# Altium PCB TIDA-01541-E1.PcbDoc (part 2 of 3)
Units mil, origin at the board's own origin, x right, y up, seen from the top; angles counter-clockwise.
Board outline 6299.21 x 6141.73 mil, 4 copper layers (Top Layer, GND, PWR, Bottom Layer), stack 79.834 mil thick; 369 components, 173 nets, 884 pads, 265 vias.
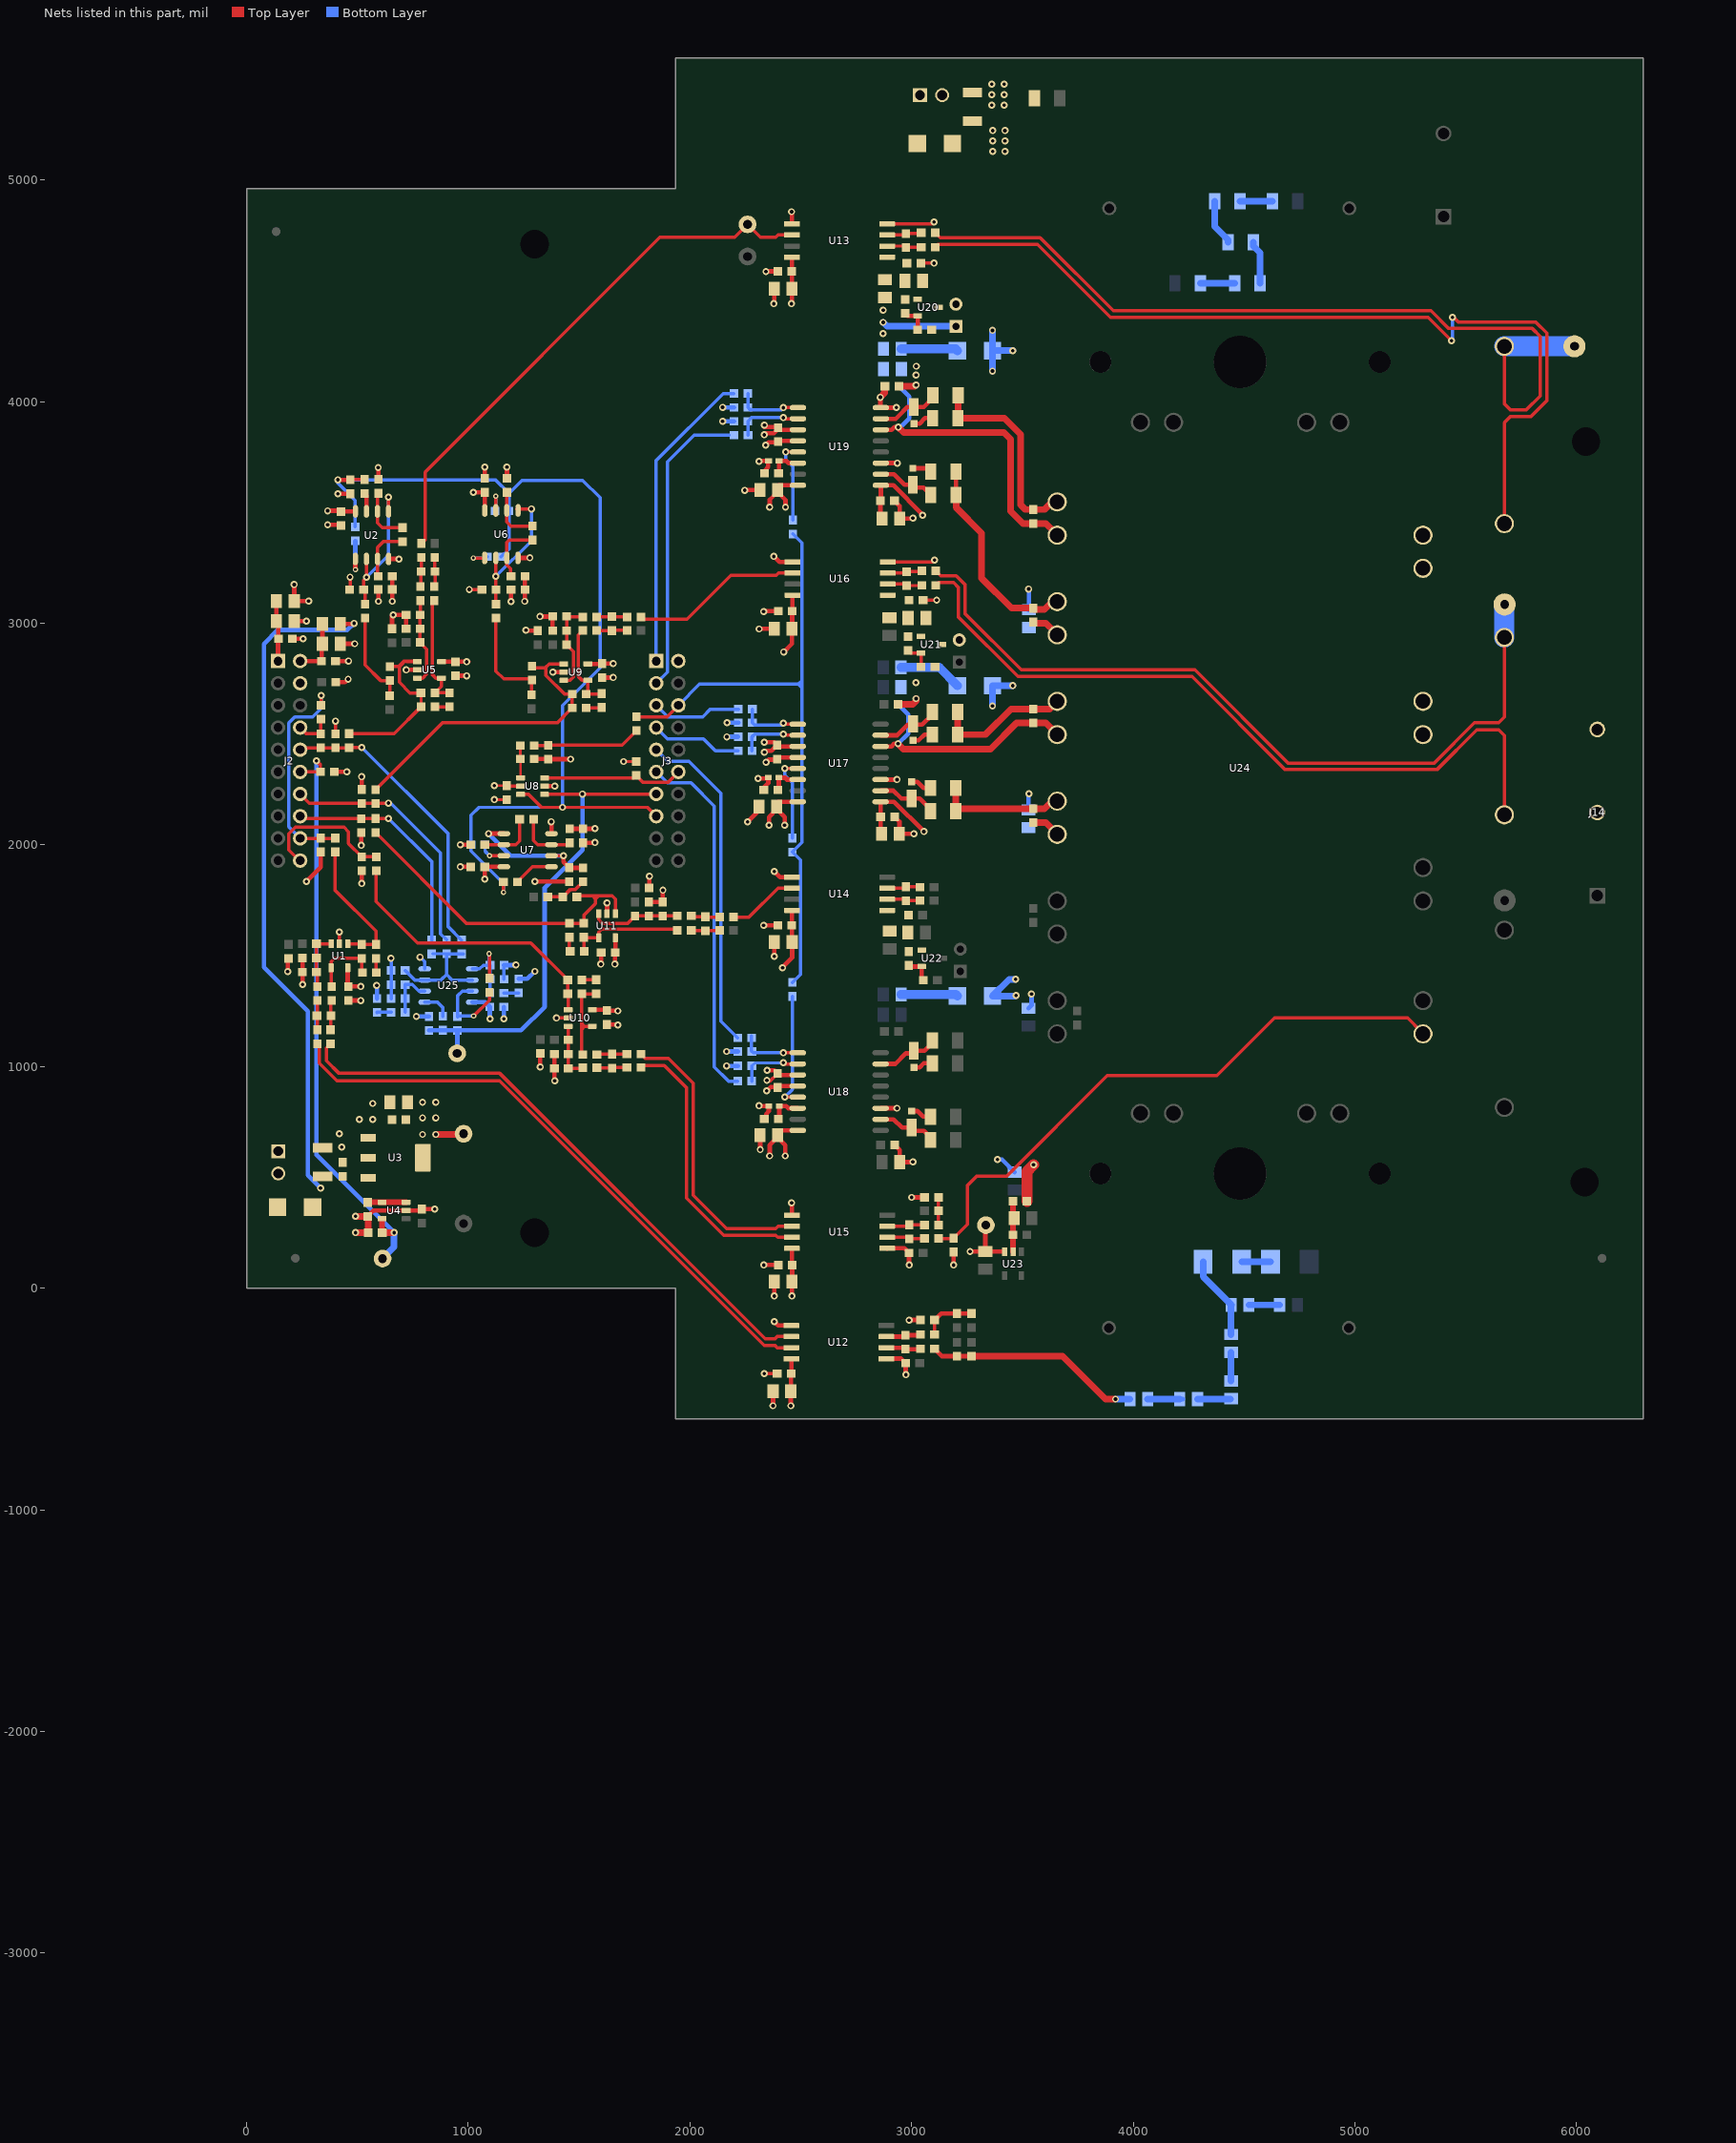
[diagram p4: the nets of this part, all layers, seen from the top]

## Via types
v1: diameter 32, hole 16, Top Layer to Bottom Layer, 258 vias
v2: diameter 24, hole 12, Top Layer to Bottom Layer, 7 vias

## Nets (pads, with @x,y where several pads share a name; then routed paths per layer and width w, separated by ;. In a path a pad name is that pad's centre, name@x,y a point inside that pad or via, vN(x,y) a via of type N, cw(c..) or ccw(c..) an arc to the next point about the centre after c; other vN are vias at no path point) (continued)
3V3: C13.1 C15.1 C23.1 C24.1 C25.1 C31.1 C32.1 C34.1 C35.1 C36.1 C44.1 C47.1 C48.1 C49.1 C55.1 C56.1 C57.1 C58.2 C59.2 C60.2 C61.2 C62.2 C63.2 C64.1 C65.2 C66.2 C67.1 C68.1 C69.2 C70.2 C108.2 R1.1 R11.2 R20.2 R35.2 R48.2 R145.1 R154.2 R157.1 TP4.1 U1.5 U2.8 U3.2 U3.4 U5.5 U6.8 U7.8 U8.5 U9.5 U10.5 U11.5 U12.8 U13.8 U14.8 U15.8 U16.8 U17.3 U17.8 U18.3 U18.8 U19.3 U19.8 U25.8 | length 4833.2
  Top Layer w12: v1(1117.08,2267.23) C36.1@1173.57,2267.23
  Top Layer w15: C36.1@1173.57,2267.23 1175.8,2265 U8.5@1235.87,2265 ; v1(2347,938) 2354.96,938 2359.86,933.1 C67.1@2395.12,968.36
  Top Layer w20: v1(214.73,3174.45) R1.1@214.73,3099.45 v1(279.73,3099.45) ; v1(365.51,3507.34) C13.1@422.01,3507.34 ; v1(411.76,3584.05) R11.2@468.27,3584.05 ; C13.1@425.51,3503.84 426.3,3504.62 U2.8@490.51,3504.62 ; U1.5@456.13,1445.27 456.13,1363.5 C15.1@458.73,1360.9 v1(515.23,1360.9) ; R20.2@657.01,3212.34 657.01,3099.34 v1(657.43,3098.91) ; U5.5@878.87,2826.85 C31.1@940.83,2826.85 ; C31.1@941.73,2825.95 v1(992.24,2825.95) ; v1@1000.83,2826.85 v1@1001.73,2825.95 ; v1@1020.79,3589.84 1021.21,3590.26 C34.1@1074.21,3590.26 U6.8@1074.21,3509.04 ; v1(1074.38,1845.91) C32.1@1074.38,1901.41 ; C32.1@1074.38,1900.91 U7.8@1160.6,1900.91 ; v1(1254.21,3098.77) 1255.71,3100.26 C35.1@1255.71,3151.76 R35.2@1255.71,3211.76 ; R48.2@1457.88,2072.4 C44.1@1517.88,2072.4 1570.41,2072.4 v1(1571.44,2073.43) ; U9.5@1539.2,2816.52 1601.97,2816.52 C48.1@1603.26,2817.81 ; U10.5@1558.87,1256.31 1620.83,1256.31 C49.1@1624.73,1252.4 1673.24,1252.4 v1(1674.73,1250.91) ; C48.1@1602.36,2818.72 C48.1@1603.26,2817.81 ; v1(1653.76,2817.81) C48.1@1603.26,2817.81 ; v1(1660.96,1461.91) 1662.45,1463.41 C47.1@1662.45,1514.91 1663.36,1515.81 U11.5@1663.36,1580.77 ; v1(2335,2463) 2379.68,2463 C64.1@2392.73,2449.95 ; v1(2335,3850) 2342.19,3857.19 2379,3857.19 2395.99,3874.18 2395.99,3878.95 2402.49,3872.45 U19.3@2486.98,3872.45 ; v1@2335,3885 C68.1@2389.94,3885 ; v1(2336,2418) 2342.64,2424.64 2368,2424.64 2392.73,2449.37 C64.1@2392.73,2449.95 ; v1(2348,983) 2380.48,983 C67.1@2395.12,968.36 ; v1(2356.48,2088.46) 2356.48,2125.48 2391.73,2160.73 C56.1@2391.73,2172.45 2391.73,2160.72 2426.99,2125.46 v1(2426.99,2088.46) ; v1(2359.61,596.86) 2359.61,645.6 C55.1@2394.86,680.85 ; v1(2359.73,3524) 2359.73,3557.18 C57.1@2394.99,3592.44 ; C55.1@2394.86,688.86 C55.1@2394.86,680.85 ; C57.1@2394.99,3600.45 C57.1@2394.99,3592.44 ; C56.1@2395.73,2194.45 U17.8@2485.98,2194.45 ; C55.1@2395.86,711.86 U18.8@2486.11,711.86 ; C67.1@2398.36,961.86 U18.3@2486.11,961.86 ; C64.1@2399.23,2443.45 C64.1@2398.23,2444.45 ; C57.1@2399.99,3622.45 U19.8@2486.98,3622.45 ; v1(2417.73,1445.45) 2417.73,1448.45 2460.73,1491.45 C62.2@2460.73,1561.45 2459.23,1562.95 C66.2@2459.23,1637.45 2460.17,1638.39 U14.8@2460.17,1704.45 ; v1(2422.73,2870.45) 2459.73,2907.45 C60.2@2459.73,2974.45 2461.23,2975.95 C69.2@2461.23,3054.45 2462.51,3055.73 U16.8@2462.51,3126.32 ; v1(2430.12,596.86) 2430.12,645.6 C55.1@2394.86,680.85 ; v1(2431,3524) 2431,3556.43 C57.1@2394.99,3592.44 ; v1(2454.73,-530.55) C58.2@2454.73,-465.55 2456.23,-464.05 C63.2@2456.23,-385.55 ; C63.2@2457.17,-385.55 U12.8@2457.17,-318.55 ; v1(2457.73,4441.45) 2459.73,4443.45 C59.2@2459.73,4509.45 2459.73,4586.95 C65.2@2459.23,4587.45 2460.17,4588.39 U13.8@2460.17,4651.58 ; v1(2459.73,-35.55) C61.2@2459.73,29.45 2461.23,30.95 C70.2@2461.23,104.45 2460.17,105.51 U15.8@2460.17,179.45 ; U17.3@2485.98,2444.45 C64.1@2398.23,2444.45 ; C64.1@2392.73,2449.95 C64.1@2398.23,2444.45
  Top Layer w30: v1(853.73,693.45) 975.73,693.45 TP4.1@978.73,696.45
  Bottom Layer w20: v1(586.76,1366.45) 587.76,1365.45 R157.1@587.76,1306.95 ; v1(765.76,1226.45) 765.25,1225.95 R154.2@822.76,1225.95 ; U25.8@1018.04,1290.45 1075.78,1290.45 C108.2@1097.24,1268.99 1097.24,1215.97 v1(1097.76,1215.45) ; R145.1@1227.73,1395.49 1265.77,1395.49 v1(1299.73,1429.45)
  other v1: 793.73,693.45 793.73,768.45 853.73,768.45 793.73,838.45 853.73,838.45 1022.79,3589.84 2336,3894
3V3_REF: C7.1 C22.1 J2.12 TP1.1 U4.5 | length 2679.6
  Top Layer w15: J2.12@241.73,2329.45 C7.1@333.24,2329.45 333.24,2360.95 v1(314.73,2379.45)
  Top Layer w20: C22.1@611.24,251.24 C22.1@611.87,250.61
  Top Layer w25: C22.1@611.24,251.24 U4.5@611.24,313.21
  Top Layer w30: C22.1@611.87,250.61 v1(665.38,250.61)
  Bottom Layer w20: v1@315.73,2378.45 v1(314.73,2379.45) 314.73,601.25 v1(665.38,250.61)
  Bottom Layer w30: TP1.1@613.38,133.61 665.38,185.61 v1(665.38,250.61)
3V3_VDC: C82.2 C91.2 C95.1 R81.1 R90.1 R106.1 TP7.1 U12.1 U15.1 U23.3 | length 757.9
  Top Layer w20: U12.1@2886.3,-318.55 2887.12,-317.73 2952.42,-317.73 C82.2@2973.24,-338.55 2973.24,-390.05 v1(2973.73,-390.55) ; U15.1@2889.3,179.45 2890.12,180.27 2967.42,180.27 C91.2@2988.24,159.45 2988.24,105.95 v1(2989.73,104.45) ; v1(2988.24,-144.05) 2988.73,-143.55 R81.1@3040.24,-143.55 ; v1(2999.73,409.45) R90.1@3058.24,409.45 ; v1(3189.73,104.45) R106.1@3189.73,162.95 ; v1(3263.33,165.32) C95.1@3332.33,165.32 ; TP7.1@3334.73,284.45 3332.33,282.05 C95.1@3332.33,165.32 ; U23.3@3419.93,164.45 3419.06,165.32 C95.1@3332.33,165.32
5V0: C5.1 C14.1 C21.1 D1.1 R7.2 U3.3 U4.3 U4.4 | length 3244.3
  Top Layer w20: R7.2@421.73,2996.45 481.73,2996.45 v1(484.73,2999.45) ; C21.1@546.38,387.1 C21.1@547.28,388.01
  Top Layer w25: C21.1@547.28,388.01 U4.4@611.24,388.01 U4.3@719.51,388.01
  Bottom Layer w20: v1(333.73,451.45) 276,509.18 276,1249 78,1447 78,2907 141,2970 455.28,2970 v1(484.73,2999.45)
+16V_GPS: C71.2 C72.2 C73.2 C74.2 C75.2 C76.2 C93.1 D8.1 D12.2 D13.2 D14.2 R110.1 U17.11 U18.11 U19.11 | length 1549
  Top Layer w20: U17.11@2860,2294.45 v1(2934,2294.45) ; U18.11@2860.12,811.86 v1(2934.13,811.86) ; U19.11@2861,3722.45 v1(2935,3722.45) ; C72.2@2922.23,3552.45 2945.73,3528.95 C73.2@2945.73,3472.45 3003.73,3472.45 v1(3005.73,3474.45) ; C74.2@2923.23,2126.45 2944.73,2104.95 C71.2@2944.73,2049.45 v1(3009.73,2049.45) ; C76.2@2923.36,645.86 2945.86,623.36 C75.2@2945.86,568.86 3004.15,568.86 v1(3005.73,570.45)
  Top Layer w50: R110.1@3519.83,392.32 3519.83,527.54 v1(3549.73,557.45)
  Bottom Layer w30: v1(3364.47,2626.71) D13.2@3364.47,2718.45 v1(3456.21,2718.45) ; v1(3364.47,4137.71) D12.2@3364.47,4229.45 ; v1(3364.47,4321.19) D12.2@3364.47,4229.45 ; v1(3456.21,4229.45) D12.2@3364.47,4229.45 ; v1(3468.73,1393.45) 3439.47,1393.45 D14.2@3364.47,1318.45 3468.73,1318.45 v1(3470.73,1320.45)
  other v1: 3365.73,5128.45 3420.73,5128.45 3365.73,5175.45 3420.73,5175.45 3365.73,5222.45 3420.73,5222.45
DISABLE: J3.6 R164.1 R165.1 R166.1 R167.2 | length 2948.1
  Top Layer w15: R167.2@1759,2578.5 1760.05,2577.45 1895.73,2577.45 J3.6@1947.73,2629.45 J3.6@1947.73,2621.45
  Bottom Layer w15: J3.6@1947.73,2629.45 2043.28,2725 2505,2725 ; R165.1@2462,1379.5 2498,1415.5 2498,1931.5 R166.1@2462,1967.5 2505,2010.5 2505,2725 ; R164.1@2464.73,3402.5 2505,3362.24 2505,2725 ; 2505,2709 2489,2725 2505,2741
DISABLE1: C46.1 R43.2 R167.1 | length 489.6
  Top Layer w15: R43.2@1297.23,2448.23 1359.24,2448.23 C46.1@1360.73,2449.72 1693.22,2449.72 R167.1@1759,2515.5
GND: C1.1 C2.1 C3.1 C4.2 C5.2 C7.2 C8.2 C9.2 C10.2 C11.2 C12.2 C13.2 C14.2 C15.2 C16.2 C17.2 C19.2 C20.2 C21.2 C22.2 C23.2 C24.2 C25.2 C26.1 C27.2 C30.2 C31.2 C32.2 C33.2 C34.2 C35.2 C36.2 C37.1 C38.1 C39.2 C40.2 C42.2 C44.2 C46.2 C47.2 C48.2 C49.2 C52.1 C53.2 C55.2 C56.2 C57.2 C58.1 C59.1 C60.1 C61.1 C62.1 C63.1 C64.2 C65.1 C66.1 C67.2 C68.2 C69.1 C70.1 C101.2 C102.2 C103.2 C104.2 C105.2 C106.2 C107.1 C108.1 C109.1 C110.1 C113.2 C114.2 C115.2 J1.1 J2.4 J3.2 R3.1 R21.1 R24.1 R32.1 R34.1 R39.1 R42.1 R44.1 R63.1 R64.1 R69.1 R70.1 R71.1 R146.2 R155.2 U1.2 U2.4 U3.1 U4.2 U5.2 U6.4 U7.4 U8.2 U9.2 U10.2 U11.2 U12.5 U13.5 U14.5 U15.5 U16.5 U17.4 U18.4 U19.4 U25.4 | length 6638.2
  Top Layer w12: v1(1117.08,2204.24) C36.2@1173.57,2204.24 C36.2@1174.33,2203.48
  Top Layer w15: C12.2@400.73,2500.95 v1(400.73,2558.45) ; U1.2@418.73,1553.54 v1(418.73,1606.4) ; C16.2@465.25,3150.95 466.76,3152.46 v1(466.76,3208.21) ; v1(1004.5,3152.19) C33.2@1061.32,3152.19 ; v1(1397.73,1218.91) U10.2@1450.6,1218.91 ; v1(1700.23,2375.95) R63.1@1757.73,2375.95 ; v1(2334.73,-385.55) C63.1@2393.24,-385.55
  Top Layer w20: C3.1@181.72,1487.91 185.23,1484.4 v1(185.23,1427.91) ; C2.1@206.23,2929.45 v1(254.73,2929.45) ; C1.1@214.73,3009.45 v1(269.73,3009.45) ; v1(252.23,1369.91) C4.2@252.23,1426.4 R3.1@252.23,1489.4 ; v1(269.73,1834.45) 334.73,1899.45 C9.2@334.73,1967.95 ; v1(365.51,3444.35) C13.2@422.01,3444.35 ; C7.2@396.23,2329.45 v1(451.73,2329.45) ; C11.2@401.23,2829.45 v1(459.73,2829.45) ; C8.2@401.5,2734 444,2734 v1(458,2748) ; C10.2@421.73,2907.45 v1(487.73,2907.45) ; C15.2@456.13,1300.5 C15.2@458.73,1297.91 v1(515.23,1297.91) ; v1(517.73,1997.45) C17.2@517.73,2054.95 ; C19.2@518.73,2249.95 v1(518.73,2307.45) ; v1(519.73,1825.45) C20.2@519.73,1882.95 ; C21.2@548.88,321.61 C21.2@546.38,324.11 571.69,349.42 572.54,349.42 573.72,350.61 U4.2@719.51,350.61 783.88,350.61 C30.2@790.38,357.1 v1(848.87,357.1) ; v1(593.66,3702.34) 594.09,3701.91 R21.1@594.09,3648.91 ; C23.2@594.02,3152.34 594.02,3099.34 v1(594.44,3098.91) ; U2.4@640.51,3290.06 687.13,3290.06 v1(687.73,3289.45) ; C26.1@655.73,2974.95 655.73,3031.45 v1(661.73,3037.45) C27.2@719.24,3037.45 R24.1@719.24,2975.45 ; v1(720.1,2789.45) U5.2@770.6,2789.45 ; C31.2@941.73,2762.95 v1(992.24,2762.95) ; v1(963.92,1900.91) C32.2@1011.39,1900.91 ; v1(963.92,2000.91) R32.1@1011.39,2000.91 ; v1@1073.79,3706.68 1074.21,3706.25 C34.2@1074.21,3653.25 ; v1@1173.79,3706.68 1174.21,3706.25 R34.1@1174.21,3653.25 ; C35.2@1192.72,3151.76 1192.72,3098.76 v1(1193.14,3098.33) ; U6.4@1224.21,3294.47 1277.21,3294.47 v1(1277.64,3294.9) ; v1(1260.07,2968.11) 1261.57,2966.62 C37.1@1313.06,2966.62 C37.1@1313.57,2966.11 ; R44.1@1297.23,2388.23 1359.24,2388.23 C46.2@1360.73,2386.73 v1(1461.73,2386.73) ; v1(1299.73,1834.45) v1(1299.73,1834.45) C42.2@1454.96,1834.41 ; v1(1323.06,3030.12) C39.2@1380.54,3030.12 ; v1(1324.73,997.91) 1323.24,999.41 1323.24,1057.91 C38.1@1324.73,1059.41 ; U8.2@1344.13,2265 v1(1390,2265) ; v1(1374.14,2104.46) 1375.17,2103.44 U7.4@1375.17,2050.91 ; R39.1@1380.57,2966.12 1380.57,3030.14 C39.2@1381.04,3030.62 ; v1(1381.43,2779.12) U9.2@1431.93,2779.12 ; R42.1@1388.24,1055.91 C40.2@1388.24,990.91 1388.24,937.4 v1(1389.73,935.91) ; C44.2@1517.88,2009.41 1570.41,2009.41 v1(1571.44,2010.43) ; v1(1597.96,1461.91) 1599.46,1463.41 C47.2@1599.46,1514.91 ; C48.2@1603.26,2754.82 v1(1653.76,2754.82) ; C49.2@1624.73,1189.41 1673.24,1189.41 v1(1674.73,1187.91) ; U11.2@1625.96,1688.04 v1(1625.96,1738.54) ; R64.1@1814.41,1742.4 C53.2@1876.41,1742.4 1876.41,1793.9 v1(1877.91,1795.39) ; C52.1@1815.4,1805.4 C52.1@1815.91,1805.91 1815.91,1857.4 v1(1817.4,1858.9) ; v1(2247.49,3599.95) 2247.99,3600.45 C57.2@2314.99,3600.45 C57.2@2317.99,3597.45 ; v1(2260,2104) 2311.73,2155.73 C56.2@2311.73,2172.45 ; v1(2307,2300) 2350.38,2300 C115.2@2353.38,2303 2353.38,2279.38 2333.24,2259.24 R70.1@2333.24,2247.45 ; v1(2311,823) 2313,821 C114.2@2355.38,821 2355.38,797.38 2343,785 ; v1(2311,3730) 2314,3733 C113.2@2354.38,3733 2353,3731.62 2353,3704 2336.5,3687.5 R71.1@2336.5,3677 ; v1(2312.23,2973.95) 2312.73,2974.45 C60.1@2379.73,2974.45 C60.1@2382.73,2971.45 ; v1(2316.86,624.86) C55.2@2316.86,688.86 ; v1(2332.24,1637.45) C66.1@2396.24,1637.45 ; v1(2332.24,3052.71) 2333.98,3054.45 C69.1@2398.24,3054.45 C69.1@2395.24,3051.45 ; v1(2333.24,104.45) C70.1@2398.24,104.45 C70.1@2399.73,102.95 ; R69.1@2335.37,763.86 2343,771.5 2343,785 ; v1(2341,3803) 2354,3816 2395.94,3816 2395.99,3815.95 2402.49,3822.45 U19.4@2486.98,3822.45 ; v1(2342.73,4586.45) 2343.73,4587.45 C65.1@2396.24,4587.45 ; 2343,785.56 2343,785 ; v1(2343,2373) 2354.45,2384.45 2390.23,2384.45 C64.2@2392.73,2386.95 ; v1@2346,892 v1(2346,891) 2348.08,891 2364.08,907 2393.48,907 C67.2@2395.12,905.37 2401.61,911.86 U18.4@2486.11,911.86 ; v1(2374.73,-530.55) C58.1@2374.73,-465.55 ; v1(2377.73,4441.45) 2379.73,4443.45 C59.1@2379.73,4509.45 ; v1(2378.73,3301.45) 2403.86,3276.32 U16.5@2462.51,3276.32 ; v1(2379.73,-150.55) 2397.73,-168.55 U12.5@2457.17,-168.55 ; v1(2379.73,-35.55) C61.1@2379.73,29.45 C61.1@2381.23,30.95 ; v1(2380.73,1497.45) C62.1@2380.73,1561.45 ; v1(2380.73,1880.45) 2406.73,1854.45 U14.5@2460.17,1854.45 ; C64.2@2400.23,2394.45 U17.4@2485.98,2394.45 ; v1(2458.67,384.45) 2460.17,382.95 U15.5@2460.17,329.45 ; v1(2458.67,4856.58) 2460.17,4855.08 U13.5@2460.17,4801.58
  Top Layer w30: v1(490.87,324.11) C21.2@546.38,324.11 ; v1(491.38,250.61) C22.2@548.88,250.61 C21.2@548.88,321.61
  Bottom Layer w15: v1(651.26,1487.95) 652.26,1486.95 C109.1@652.26,1433.45 C110.1@652.26,1369.45 R155.2@652.26,1306.45 ; v1(782.76,1493.45) 803.47,1472.73 U25.4@803.47,1440.45 ; R146.2@1161.23,1393.99 C107.1@1161.23,1456.99
  Bottom Layer w20: C108.1@1160.23,1268.99 1160.23,1215.97 v1(1160.75,1215.45) ; C107.1@1161.23,1456.99 1214.21,1456.99 v1(1215.19,1457.97) ; v1(2147.19,3910.99) C106.2@2198.24,3910.99 ; v1(2147.19,3973.99) C105.2@2198.24,3973.99 ; v1(2165.19,1002.99) C104.2@2216.24,1002.99 ; v1(2165.19,1067.99) C103.2@2216.24,1067.99 ; v1(2166.19,2487.65) C102.2@2217.24,2487.65 ; v1(2167.19,2550.99) C101.2@2218.24,2550.99
  other v1: 428.73,636.45 418.73,696.45 508.73,761.45 568.73,761.45 568.73,833.45 1074.15,3704.65 1174.15,3704.65
GND1: C93.2 J4.2 R111.1 R132.2 R133.2 R134.2 R135.2 | length 345.9
  Bottom Layer w20: v1@3383.73,576.45 v1(3387.73,580.45) 3407.73,580.45 R135.2@3464.73,523.45 ; R134.2@3527.73,1262.45 3540.73,1275.45 v1(3540.73,1327.45) ; R133.2@3527.73,2157.45 3527.73,2229.45 v1(3528.73,2230.45) ; R132.2@3527.73,3059.45 R132.2@3528.73,3060.45 3528.73,3153.45 v1(3527.73,3154.45)
  other v1: 3361.73,5337.45 3416.73,5337.45 3361.73,5384.45 3416.73,5384.45 3361.73,5431.45 3416.73,5431.45
GND_FAULT: J3.13 R149.2 R152.2 R154.1 TP2.1 U8.1 | length 2197.2
  Top Layer w15: U8.1@1344.13,2227.6 1512.88,2227.6 v1(1514.73,2229.45) J3.13@1847.73,2229.45
  Bottom Layer w20: R154.1@822.76,1162.95 823.31,1163.5 R152.2@885,1163.5 ; R152.2@885,1163.45 942.26,1163.45 R149.2@942.76,1162.95 ; TP2.1@949.73,1059.45 950.73,1060.45 R149.2@950.73,1162.95 1238.24,1162.95 1344.73,1269.45 1344.73,1806.4 1514.73,1976.4 v1(1514.73,2229.45)
I_U: C12.1 J2.10 R6.2 R13.2 R148.1 | length 1337
  Top Layer w15: J2.10@241.73,2429.45 250.24,2437.95 R6.2@334.73,2437.95 C12.1@400.73,2437.95 461.73,2437.95 R13.2@462.73,2438.95 463.23,2439.45 v1(519.73,2439.45)
  Bottom Layer w15: v1(519.73,2439.45) 909.73,2049.45 909.73,1630.95 R148.1@969.73,1570.95
I_V: C19.1 J2.14 R17.2 R150.1 | length 1153.3
  Top Layer w15: J2.14@241.73,2229.45 283.23,2187.95 507.74,2187.95 C19.1@518.73,2176.95 ; C19.1@518.73,2186.95 R17.2@580.73,2186.95 ; R17.2@581.73,2185.95 R17.2@580.73,2186.95 ; v1(639.73,2188.46) 582.24,2188.46 R17.2@580.73,2186.95
  Bottom Layer w15: v1(639.73,2188.46) 650.73,2188.46 874.73,1964.45 874.73,1598.97 R150.1@901.76,1571.95
I_W: C17.1 J2.16 R16.2 R153.1 | length 1032.7
  Top Layer w15: J2.16@241.73,2129.45 253.24,2117.95 C17.1@517.73,2117.95 580.73,2117.95 R16.2@581.73,2118.95 582.24,2119.45 v1(639.73,2119.45)
  Bottom Layer w15: v1(639.73,2119.45) 834.73,1924.45 R153.1@834.73,1570.95
MODULE_TEMP: C20.1 J2.20 R19.2 | length 637.9
  Top Layer w15: J2.20@241.73,1929.45 237.73,1929.45 189.73,1977.45 189.73,2049.45 219.73,2079.45 439.73,2079.45 459.73,2059.45 459.73,2005.95 C20.1@519.73,1945.95 R19.2@584.73,1945.95
NetC1_2: C1.2 C2.2 J2.1 R1.2 | length 274.1
  Top Layer w20: R1.2@134.73,3099.45 C1.2@134.73,3009.45 143.24,3000.95 C2.2@143.24,2929.45 141.73,2927.95 J2.1@141.73,2829.45
NetC4_1: C4.1 R2.2 R3.2 R4.2 U1.3 | length 261.4
  Top Layer w15: R4.2@318.73,1360.9 318.73,1422.9 C4.1@315.23,1426.4 R3.2@315.23,1489.4 R2.2@315.23,1554.4 316.09,1553.54 U1.3@381.33,1553.54
NetC6_1: C6.1 R9.2 R10.1 | length 134.1
  Top Layer w15: R9.2@378.73,1165.9 378.73,1227.91 C6.1@380.23,1229.4 380.23,1294.4 R10.1@383.73,1297.91
NetC6_2: C6.2 R4.1 R5.2 | length 133.2
  Top Layer w15: R5.2@318.73,1165.9 318.73,1227.91 C6.2@317.23,1229.4 318.73,1230.9 R4.1@318.73,1297.91
NetC10_1: C10.1 C11.1 J2.2 R7.1 | length 265
  Top Layer w20: J2.2@241.73,2829.45 C11.1@338.24,2829.45 338.24,2903.95 C10.1@341.73,2907.45 R7.1@341.73,2996.45
NetC16_1: C16.1 R15.2 U2.2 U2.5 | length 680.6
  Top Layer w15: R15.2@534.73,3085.95 534.73,3144.45 C16.1@528.24,3150.95 528.24,3194.68 v1(540.51,3206.95) U2.2@540.51,3290.06 ; v1(640.09,3569.42) 640.09,3505.05 U2.5@640.51,3504.62
  Bottom Layer w15: v1(540.51,3206.95) 640.09,3306.53 v1(640.09,3569.42)
NetC18_1: C18.1 R10.2 R14.1 U1.4 | length 321.6
  Top Layer w15: R10.2@383.73,1360.9 381.33,1363.3 U1.4@381.33,1445.27 381.33,1473 396.23,1487.91 C18.1@518.73,1487.91 518.73,1427.91 R14.1@522.23,1424.4
NetC18_2: C18.2 R12.1 R18.2 U1.1 | length 622
  Top Layer w15: R12.1@399.73,1967.95 399.73,1794.45 583.73,1610.45 R18.2@583.73,1550.9 C18.2@518.73,1550.9 516.09,1553.54 U1.1@456.13,1553.54
NetC27_1: C27.1 R24.2 R25.2 R26.2 U5.3 | length 393.9
  Top Layer w15: U5.3@770.6,2752.05 793.45,2752.05 812.73,2771.33 812.73,2882.95 R25.2@782.23,2913.45 R24.2@782.23,2975.45 C27.1@782.23,3037.45 783.61,3038.83 R26.2@783.61,3101.95
NetC28_1: C28.1 R29.2 R31.1 U5.4 | length 529.8
  Top Layer w15: R29.2@846.61,3101.95 836.73,3092.08 836.73,2769.45 854.13,2752.05 U5.4@878.87,2752.05 878.87,2715.09 C28.1@849.73,2685.95 ; C28.1@849.23,2685.45 C28.1@849.73,2685.95 ; R31.1@914.73,2685.95 C28.1@849.73,2685.95
NetC28_2: C28.2 R13.1 R27.2 R168.2 U5.1 | length 838.8
  Top Layer w15: R13.1@462.73,2501.95 665.73,2501.95 R27.2@787.24,2623.45 787.24,2684.45 C28.2@786.24,2685.45 736.55,2685.45 688.6,2733.4 688.6,2804.5 ; R168.2@646,2804.5 688.6,2804.5 ; 707.05,2820.95 690.59,2804.5 688.6,2804.5 ; 721,2826.85 U5.1@770.6,2826.85 768.45,2829 709,2829 688.6,2808.6 688.6,2804.5
NetC29_1: C29.1 R29.1 R30.2 | length 133.2
  Top Layer w15: R29.1@848.61,3164.95 850.1,3166.44 C29.1@850.1,3233.45 848.61,3234.95 R30.2@848.61,3296.95
NetC29_2: C29.2 R26.1 R28.2 | length 134.1
  Top Layer w15: R26.1@783.61,3164.95 787.11,3168.45 C29.2@787.11,3233.45 788.61,3234.95 R28.2@788.61,3296.95
NetC33_1: C33.1 R33.2 U6.2 U6.5 | length 647.2
  Top Layer w15: v1@1123.4,3212.19 v1(1124.21,3211.37) ; U6.2@1124.21,3294.47 v1(1124.21,3211.37) ; R33.2@1124.73,3085.95 1124.32,3086.36 C33.1@1124.32,3152.19 1124.32,3211.27 v1(1124.21,3211.37) ; U6.5@1218.8,3514.45 1283.17,3514.45 v1(1284.6,3515.88)
  Bottom Layer w15: v1(1124.21,3211.37) 1284.6,3371.76 v1(1284.6,3515.88)
NetC39_1: C39.1 R39.2 R40.2 R51.2 U9.3 | length 407.6
  Top Layer w15: U9.3@1431.93,2741.72 1457.66,2741.72 1474.06,2758.12 1474.06,2872.62 R40.2@1443.56,2903.12 R39.2@1443.56,2966.12 1444.03,2966.59 C39.1@1444.03,3030.62 1446.66,3027.99 R51.2@1516.26,3027.99
NetC40_1: C40.1 R41.2 R42.2 R54.2 U10.3 | length 257.9
  Top Layer w15: U10.3@1450.6,1181.5 1451.23,1180.88 R41.2@1451.23,1120.91 R42.2@1451.23,1055.91 1451.23,1045.91 C40.1@1451.23,990.91 1513.24,990.91 R54.2@1516.78,994.45
NetC41_1: C41.1 R53.2 R56.1 U10.4 | length 406.2
  Top Layer w15: 1512.03,1193.81 1524.33,1181.5 ; R53.2@1514.48,1056.75 1512.03,1059.2 1512.03,1169.2 ; U10.4@1558.87,1181.5 1524.33,1181.5 ; R56.1@1576.53,1328.41 1576.03,1327.91 C41.1@1512.03,1327.91 1512.03,1169.2 ; 1512.03,1169.2 1524.33,1181.5
NetC41_2: C41.2 R19.1 R45.2 U10.1 | length 1259.6
  Top Layer w15: 584.73,1860.27 584.73,1744.45 771.18,1558 1281.94,1558 R45.2@1449.04,1390.91 C41.2@1449.04,1327.91 ; U10.1@1450.6,1256.31 C41.2@1450.6,1326.34
NetC42_1: C42.1 R55.2 U7.2 U7.5 | length 629.8
  Top Layer w15: U7.2@1375.17,1950.91 v1(1429.73,1950.91)
  Top Layer w20: v1@1091.46,2050.91 U7.5@1160.6,2050.91 ; v1(1429.73,1950.91) 1429.73,1922.62 C42.1@1454.96,1897.4 1455.96,1896.4 R55.2@1516.96,1896.4
  Bottom Layer w20: v1(1091.44,2050.88) 1191.41,1950.91 v1(1429.73,1950.91)
NetC43_1: C43.1 R52.2 R57.1 U9.4 | length 415.2
  Top Layer w15: R52.2@1507.13,2977.12 R52.2@1516.26,2967.99 1495.43,2947.17 1497.06,2945.54 1497.06,2759.12 1514.47,2741.72 U9.4@1539.2,2741.72 1539.2,2687.76 C43.1@1531.76,2680.32 1598.52,2680.32 R57.1@1601.04,2682.84
NetC43_2: C43.2 R17.1 R50.2 R169.2 U9.1 | length 1446.1
  Top Layer w15: R17.1@581.73,2248.95 883.16,2550.37 1400.82,2550.37 R50.2@1468.76,2618.32 C43.2@1468.76,2680.32 1434.68,2680.32 1349.93,2765.07 1349.93,2797.83 1348.1,2799.66 ; R169.2@1287,2806.5 1293.84,2799.66 1348.1,2799.66 ; U9.1@1431.93,2816.52 U9.1@1430.93,2816.52 1364.96,2816.52 1348.1,2799.66
NetC45_1: C45.1 R49.1 R66.2 U11.4 | length 521.6
  Top Layer w15: R49.1@1522.45,1519.91 1520.96,1521.4 C45.1@1520.96,1583.41 1523.59,1580.77 U11.4@1588.55,1580.77 1588.55,1607.5 1600.96,1619.91 1937.78,1619.91 R66.2@1943.24,1614.45
NetC45_2: C45.2 R16.1 R47.2 R170.2 U11.1 | length 1528
  Top Layer w15: R16.1@581.73,2055.95 991.28,1646.4 R47.2@1455.96,1646.4 C45.2@1520.96,1646.4 1521,1646.45 1521,1682 ; R170.2@1489.5,1765 1494.4,1769.91 1560.09,1769.91 ; 1520.96,1681.96 1521,1682 ; U11.1@1663.36,1689.04 1663.36,1755.01 1648.32,1770.04 1612.91,1770.04 1612.77,1769.91 1587.91,1769.91 ; 1521,1682 1574,1735 1574,1756 ; 1560.09,1769.91 1574,1756 ; 1560.09,1769.91 1587.91,1769.91 ; 1574,1756 1587.91,1769.91
NetC50_1: C50.1 R52.1 R61.2 | length 138.2
  Top Layer w15: R52.1@1579.25,2967.99 1580.74,2966.5 C50.1@1647.75,2966.5 1649.25,2967.99 R61.2@1716.26,2967.99
NetC50_2: C50.2 R51.1 R60.2 | length 138.2
  Top Layer w15: R51.1@1579.25,3027.99 1646.26,3027.99 C50.2@1647.75,3029.49 1649.25,3027.99 R60.2@1716.26,3027.99
NetC51_1: C51.1 R53.1 R58.2 | length 136.3
  Top Layer w10: C51.1@1648.28,1055.95 C51.1@1648.77,1055.45
  Top Layer w15: R53.1@1579.77,1054.45 1581.27,1055.95 C51.1@1648.28,1055.95 ; C51.1@1648.77,1055.45 R58.2@1715.28,1055.45
NetC51_2: C51.2 R54.1 R59.2 | length 137.2
  Top Layer w15: R54.1@1579.77,994.45 1581.27,992.95 C51.2@1648.28,992.95 1650.77,995.45 R59.2@1715.28,995.45
NetC53_1: C53.1 R62.2 R64.2 R65.2 U11.3 | length 401.1
  Top Layer w15: U11.3@1588.55,1688.04 1588.55,1662.31 1604.96,1645.91 1718.91,1645.91 R62.2@1752.41,1679.41 R64.2@1814.41,1679.41 C53.1@1876.41,1679.41 R65.2@1943.24,1679.45 R65.2@1943.24,1679.45
NetC54_1: C54.1 R66.1 R68.2 | length 126.1
  Top Layer w15: R66.1@2006.23,1614.45 2007.73,1612.95 C54.1@2069.73,1612.95 R68.2@2131.74,1612.95
NetC54_2: C54.2 R65.1 R67.2 | length 129.1
  Top Layer w15: R65.1@2006.23,1679.45 2009.73,1675.95 C54.2@2069.73,1675.95 2071.23,1674.45 R67.2@2133.24,1674.45
NetC80_2: C80.2 C87.2 R72.2 R75.1 U13.1 U20.1
NetC81_1: C81.1 R83.2 U12.2 | length 157.2
  Top Layer w20: U12.2@2886.3,-268.55 2965.24,-268.55 C81.1@2971.73,-275.05 3038.74,-275.05 R83.2@3040.24,-273.55
NetC81_2: C81.2 R82.2 U12.3 | length 158.1
  Top Layer w20: U12.3@2886.3,-218.55 2965.24,-218.55 C81.2@2971.73,-212.05 3036.73,-212.05 R82.2@3040.24,-208.55
NetC83_1: C83.1 R86.2 U13.2 | length 157.2
  Top Layer w15: U13.2@2889.3,4701.58 2968.24,4701.58 C83.1@2974.73,4695.08 2976.23,4696.58 R86.2@3043.24,4696.58
NetC83_2: C83.2 R85.2 U13.3 | length 153.1
  Top Layer w15: U13.3@2889.3,4751.58 C83.2@2968.24,4751.58 ; C83.2@2974.73,4758.07 R85.2@3039.73,4758.07
  Top Layer w20: C83.2@2968.24,4751.58 C83.2@2974.73,4758.07
NetC84_1: C84.1 R80.2 U14.2 | length 152.2
  Top Layer w15: U14.2@2889.3,1754.45 2968.24,1754.45 C84.1@2974.73,1747.95 3036.74,1747.95 R80.2@3038.24,1749.45
NetC84_2: C84.2 R79.2 U14.3 | length 152.2
  Top Layer w15: U14.3@2889.3,1804.45 2968.24,1804.45 C84.2@2974.73,1810.95 3036.74,1810.95 R79.2@3038.24,1809.45
NetC85_2: C85.2 C89.2 R74.2 R77.1 U14.1 U22.1
NetC86_2: C86.2 C90.2 R73.2 R76.1 U16.1 U21.1
NetC88_1: C88.1 R88.2 U16.2 | length 157.2
  Top Layer w15: U16.2@2891.65,3176.32 2970.58,3176.32 C88.1@2977.08,3169.83 3044.09,3169.83 R88.2@3045.58,3171.32
NetC88_2: C88.2 R87.2 U16.3 | length 158.1
  Top Layer w15: U16.3@2891.65,3226.32 2970.58,3226.32 C88.2@2977.08,3232.82 3042.08,3232.82 R87.2@3045.58,3236.32
NetC92_1: C92.1 R93.2 U15.2 | length 172.2
  Top Layer w15: U15.2@2889.3,229.45 2983.24,229.45 C92.1@2989.73,222.95 2991.23,224.45 R93.2@3058.24,224.45
NetC92_2: C92.2 R92.2 U15.3 | length 172.2
  Top Layer w15: U15.3@2889.3,279.45 2983.24,279.45 C92.2@2989.73,285.95 3056.74,285.95 R92.2@3058.24,284.45
NetC94_2: C94.2 R81.2 R82.1 R107.2 | length 238.7
  Top Layer w15: R82.1@3103.23,-208.55 R81.2@3103.23,-143.55
  Top Layer w20: R81.2@3103.23,-143.55 3132.73,-114.05 R107.2@3199.73,-114.05 ; R107.2@3204.73,-114.05 C94.2@3269.73,-114.05
NetC96_1: C96.1 C97.1 R110.2 U23.2 | length 232.6
  Top Layer w25: R110.2@3456.84,392.32 3456.84,321.81 C96.1@3462.33,316.32 3456.84,310.82 C97.1@3456.84,240.32 3457.33,239.82 U23.2@3457.33,164.45
NetC107_2: C107.2 R146.1 R147.2 R151.1 U25.5 | length 377.7
  Top Layer w15: v2(1094,1509) 1095.73,1507.27 R151.1@1095.73,1398.22
  Bottom Layer w15: U25.5@1018.04,1440.45 1050.76,1440.45 1067.3,1456.99 C107.2@1098.24,1456.99 ; v2(1094,1509) 1094,1461.23 C107.2@1098.24,1456.99 ; R147.2@1097.24,1331.99 1097.24,1392.99 R146.1@1098.24,1393.99 C107.2@1098.24,1456.99
NetC109_2: C109.2 R148.2 R150.2 R153.2 U25.3 U25.6 | length 573.2
  Bottom Layer w15: C109.2@715.25,1433.45 758.25,1390.45 U25.3@803.47,1390.45 876.76,1390.45 901.76,1415.45 ; R153.2@839.76,1508.95 R150.2@901.76,1508.95 ; R148.2@977.76,1507.95 902.76,1507.95 R150.2@901.76,1508.95 ; U25.6@1018.04,1390.45 926.76,1390.45 901.76,1415.45 ; 901.76,1415.45 R150.2@901.76,1508.95
NetC110_2: C110.2 R155.1 R156.2 U25.2 | length 225.2
  Bottom Layer w15: R156.2@715.25,1244.45 R155.1@715.25,1306.45 C110.2@715.25,1369.45 747.76,1369.45 776.76,1340.45 U25.2@803.47,1340.45
NetC113_1: C113.1 R71.2 U19.6 | length 146.6
  Top Layer w20: R71.2@2399.5,3677 2401.62,3679.13 C113.1@2401.62,3733 2435,3733 2445.55,3722.45 U19.6@2486.98,3722.45
NetC114_1: C114.1 R69.2 U18.6 | length 146.2
  Top Layer w20: R69.2@2398.36,763.86 2402.62,768.13 C114.1@2402.62,821 2434,821 2443.14,811.86 U18.6@2486.11,811.86
NetC115_1: C115.1 R70.2 U17.6 | length 146.3
  Top Layer w20: R70.2@2396.23,2247.45 2400.62,2251.84 C115.1@2400.62,2303 2429,2303 2437.55,2294.45 U17.6@2485.98,2294.45
NetD1_2: D1.2 J1.2
NetD3_1: D3.1 R102.1 U17.15 | length 284.7
  Top Layer w20: U17.15@2860,2494.45 2935.73,2494.45 2983.39,2542.1 3047.39,2542.1 3093.9,2588.62 R102.1@3093.9,2600.45
NetD3_2: D3.2 R100.1 | length 100.2
  Top Layer w20: D3.2@3006.23,2471.24 3031.24,2471.24 3057.45,2497.45 R100.1@3093.65,2497.45 R100.1@3092.3,2498.8
NetD4_1: D4.1 R103.1 U18.15 | length 280.2
  Top Layer w20: U18.15@2860.12,1011.86 2926.94,1011.86 2974.6,1059.52 D4.1@3010,1059.52 ; D4.1@3010,1070.59 3058.59,1070.59 3094.03,1106.03 R103.1@3094.03,1117.86
NetD4_2: D4.2 R101.1 | length 91.7
  Top Layer w20: D4.2@3010,995.79 3035.79,995.79 3054.86,1014.86 R101.1@3093.77,1014.86
NetD5_1: D5.1 R95.1 U17.10 | length 268.5
  Top Layer w20: U17.10@2860,2244.45 2918.73,2244.45 2953.77,2209.41 D5.1@3000,2209.41 3035.59,2209.41 3084.9,2160.1 R95.1@3084.9,2151.45
NetD5_2: D5.2 R94.1 | length 96.4
  Top Layer w20: D5.2@3000,2284.21 3025.79,2284.21 3053.55,2256.45 R94.1@3084.9,2256.45
NetD6_1: D6.1 R97.1 U18.10 | length 269.9
  Top Layer w20: U18.10@2860.12,761.86 2918.86,761.86 2956.31,724.41 D6.1@3000,724.41 3014.41,710 3055,710 3085.03,679.97 R97.1@3085.03,668.86
NetD6_2: D6.2 R96.1 | length 95.5
  Top Layer w20: D6.2@3000,799.21 3025.79,799.21 3051.14,773.86 R96.1@3085.03,773.86
NetD7_1: D7.1 R105.1 U19.15 | length 297.3
  Top Layer w20: U19.15@2861,3922.45 2927.82,3922.45 2964.73,3959.37 2964.73,3959.73 2980.59,3975.59 D7.1@3010,3975.59 3054.78,3975.59 3094.9,4015.72 R105.1@3094.9,4028.45 R105.1@3094.9,4016.62
NetD7_2: D7.2 R104.1 | length 96.8
  Top Layer w20: D7.2@3010,3900.79 3035.79,3900.79 3060.45,3925.45 R104.1@3094.65,3925.45 R104.1@3093.3,3926.8
NetD8_2: D8.2 J4.1
NetD9_1: D9.1 R99.1 U19.10 | length 263.4
  Top Layer w20: U19.10@2861,3672.45 2919.73,3672.45 2967.77,3624.41 D9.1@3005,3624.41 3017.79,3611.62 3053.73,3611.62 R99.1@3085.9,3579.45
NetD9_2: D9.2 R98.1 | length 87
  Top Layer w20: D9.2@3005,3699.21 3071.14,3699.21 R98.1@3085.9,3684.45
NetD10_2: D10.2 D11.1 | length 130
  Bottom Layer w30: D11.1@4488.75,119.45 D10.2@4618.73,119.45
NetD11_2: D11.2 R125.1 R127.2 | length 381
  Bottom Layer w20: R127.2@4440.73,-209.54 R127.2@4441.74,-210.55
  Bottom Layer w30: D11.2@4314.73,119.45 4314.73,51.45 R125.1@4441.73,-75.55 ; R127.2@4440.73,-209.54 R125.1@4440.73,-77.54
NetD12_1: D12.1 R136.2 | length 257.6
  Bottom Layer w40: R136.2@2952.73,4237.45 3198.99,4237.45 D12.1@3206.99,4229.45
NetD13_1: D13.1 R138.2 | length 289.2
  Bottom Layer w40: R138.2@2951.73,2800.45 3124.99,2800.45 D13.1@3206.99,2718.45
NetD14_1: D14.1 R137.2 | length 257.8
  Bottom Layer w40: R137.2@2951.86,1324.86 3200.58,1324.86 D14.1@3206.99,1318.45
NetJ2_8: J2.8 R6.1 R8.1 | length 171.2
  Top Layer w15: J2.8@241.73,2529.45 270.24,2500.95 R6.1@334.73,2500.95 334.73,2565.95 R8.1@335.73,2566.95
NetJ3_1: J3.1 R144.2 | length 1380.6
  Bottom Layer w15: J3.1@1847.73,2829.45 1847.73,3734.45 2149.73,4036.45 R144.2@2198.24,4036.45
NetJ3_3: J3.3 R143.2 | length 1347.9
  Bottom Layer w15: J3.3@1847.73,2729.45 1897.73,2779.45 1897.73,3727.45 2019.28,3848.99 2176.55,3848.99
NetJ3_5: J3.5 R139.2 | length 406.5
  Bottom Layer w15: J3.5@1847.73,2629.45 1899.73,2577.45 2057.73,2577.45 2092.73,2612.45 R139.2@2218.24,2612.45
NetJ3_7: J3.7 R140.2 | length 413
  Bottom Layer w15: J3.7@1847.73,2529.45 1898.73,2478.45 2060.73,2478.45 2114.73,2424.45 R140.2@2217.24,2424.45
NetJ3_9: J3.9 R141.2 | length 1507.9
  Bottom Layer w15: J3.9@1847.73,2429.45 1899.73,2377.45 1994.73,2377.45 2139.73,2232.45 2139.73,1204.95 R141.2@2215.24,1129.45
NetJ3_11: J3.11 R142.2 | length 1634.5
  Bottom Layer w15: J3.11@1847.73,2329.45 1897.73,2279.45 2004.73,2279.45 2109.73,2174.45 2109.73,997.99 2173.28,934.45 R142.2@2215.24,934.45
NetR5_1: R5.1 U12.7 | length 2769.5
  Top Layer w15: R5.1@323.73,1097.91 R5.1@318.73,1102.91 ; R5.1@325.73,1095.91 R5.1@318.73,1102.91 ; U12.7@2457.17,-268.55 2393.61,-268.55 2383.73,-258.68 2334.73,-258.68 1141.06,935 408,935 328.27,1014.73 328.27,1093.36 R5.1@318.73,1102.91
NetR9_1: R9.1 U12.6 | length 2705.8
  Top Layer w15: R9.1@378.73,1102.91 359.93,1084.11 359.93,1026 416.93,969 1142.06,969 2339.73,-228.68 2383.73,-228.68 2393.86,-218.55 U12.6@2457.17,-218.55
NetR14_2: R14.2 R18.1 | length 64.1
  Top Layer w15: R18.1@583.73,1487.91 583.73,1425.9 R14.2@585.23,1424.4
NetR15_1: R15.1 R22.2 R168.1 | length 420.3
  Top Layer w15: R15.1@534.73,3022.95 534.73,2811.27 604.5,2741.5 R168.1@646,2741.5 646,2674.5 R22.2@645,2673.5
NetR20_1: R20.1 R23.2 U2.3 | length 254.3
  Top Layer w15: R20.1@594.02,3212.34 590.51,3215.84 U2.3@590.51,3290.06 590.51,3341.84 616.59,3367.92 R23.2@703.09,3367.92
NetR21_2: R21.2 R23.1 U2.6 | length 256.7
  Top Layer w15: R21.2@594.09,3585.92 590.51,3582.35 U2.6@590.51,3504.62 590.51,3451.99 611.59,3430.91 R23.1@703.09,3430.91
NetR27_1: R27.1 R31.2 | length 64.7
  Top Layer w15: R27.1@850.23,2623.45 850.73,2622.95 R31.2@914.73,2622.95
NetR28_1: R28.1 TP5.1 U13.6 | length 2475.1
  Top Layer w15: R28.1@788.61,3359.95 804.73,3376.07 804.73,3681.73 1864.45,4741.45 2201.73,4741.45 TP5.1@2259.73,4799.45 2317.73,4741.45 2386.73,4741.45 2396.86,4751.58 U13.6@2460.17,4751.58
NetR32_2: R32.2 R36.1 U7.6 | length 261.8
  Top Layer w15: R32.2@1074.38,2000.91 U7.6@1160.6,2000.91 1213.92,2000.91 1231.39,2018.38 R36.1@1231.39,2115.91
NetR33_1: R33.1 R38.2 R169.1 | length 485.7
  Top Layer w15: R33.1@1124.73,3022.95 1124.73,2784.27 1160,2749 1281.5,2749 R169.1@1287,2743.5 1285,2741.5 R38.2@1285,2676.5
NetR34_2: R34.2 R37.1 U6.6 | length 256.4
  Top Layer w15: R34.2@1174.21,3590.26 U6.6@1174.21,3509.04 1174.21,3456.41 1192.37,3438.25 R37.1@1289.21,3438.25
NetR35_1: R35.1 R37.2 U6.3 | length 279.7
  Top Layer w15: R35.1@1192.72,3211.76 1190.08,3214.4 1190.08,3246.84 1174.21,3262.7 U6.3@1174.21,3294.47 1174.21,3364.26 1185.21,3375.26 R37.2@1289.21,3375.26
NetR36_2: R36.2 R48.1 U7.3 | length 270.6
  Top Layer w15: R36.2@1294.38,2115.91 1294.38,2020.48 1313.96,2000.91 U7.3@1375.17,2000.91 1449.38,2000.91 R48.1@1457.88,2009.41
NetR43_1: R43.1 R44.2 U8.4 | length 146.5
  Top Layer w12: R43.1@1234.24,2448.23 R44.2@1234.24,2388.23 1235.87,2386.6 U8.4@1235.87,2302.4
NetR45_1: R45.1 R56.2 | length 64.7
  Top Layer w15: R45.1@1512.03,1390.91 1576.04,1390.91 R56.2@1576.53,1391.4
NetR46_2: R46.2 R55.1 R170.1 | length 186.8
  Top Layer w15: R46.2@1358.5,1765 R170.1@1426.5,1765 1460.73,1799.23 1482.77,1799.23 R55.1@1516.96,1833.41
NetR47_1: R47.1 R49.2 | length 65
  Top Layer w15: R47.1@1455.96,1583.41 1455.96,1523.41 R49.2@1459.46,1519.91
NetR50_1: R50.1 R57.2 | length 69.9
  Top Layer w15: R50.1@1531.76,2618.32 1599.51,2618.32 R57.2@1601.04,2619.84
NetR58_1: R58.1 U15.6 | length 1307.5
  Top Layer w15: R58.1@1778.28,1055.45 1797.08,1036.65 1902.53,1036.65 2014.73,924.45 2014.73,419.45 2164.86,269.32 2386.73,269.32 2396.86,279.45 U15.6@2460.17,279.45
NetR59_1: R59.1 U15.7 | length 1315.4
  Top Layer w15: R59.1@1783.28,1000.45 R59.1@1778.28,995.45 ; R59.1@1785.28,1002.45 R59.1@1778.28,995.45 ; U15.7@2460.17,229.45 2396.61,229.45 2386.73,239.32 2152.43,239.32 1984.73,407.02 1984.73,904.45 1884.19,1004.99 1787.82,1004.99 R59.1@1778.28,995.45
NetR60_1: R60.1 U16.6 | length 780.4
  Top Layer w15: R60.1@1784.25,3022.99 R60.1@1779.25,3027.99 1788.79,3018.45 1987.31,3018.45 2185.05,3216.2 2389.08,3216.2 2399.21,3226.32 U16.6@2462.51,3226.32
NetR67_1: R67.1 U14.6 | length 317.8
  Top Layer w15: R67.1@2196.23,1674.45 2266.86,1674.45 2396.86,1804.45 U14.6@2460.17,1804.45
NetR75_2: R75.2 R78.1 U20.2 | length 124
  Top Layer w20: R75.2@2970.73,4397.95 2981.64,4387.05 U20.2@3027.49,4387.05 3027.49,4324.7 R78.1@3027.24,4324.45
NetR76_2: R76.2 R84.1 U21.2 | length 125.2
  Top Layer w15: R76.2@2983.73,2876.95 2994.64,2866.05 U21.2@3041.49,2866.05 3042.24,2865.3 R84.1@3042.24,2803.45
NetR77_2: R77.2 R89.1 U22.2 | length 125.6
  Top Layer w20: R77.2@2986.73,1455.95 2991.64,1451.05 U22.2@3045.49,1451.05 3045.49,1397.2 R89.1@3053.24,1389.45
NetR83_1: R83.1 R108.2 R109.2 R131.1 | length 975.5
  Top Layer w20: R83.1@3103.23,-273.55 3136.73,-307.05 R108.2@3204.73,-307.05 R109.2@3269.73,-307.05
  Top Layer w30: R109.2@3269.73,-307.05 3681.23,-307.05 3874.73,-500.55 v1(3919.73,-500.55)
  Bottom Layer w30: v1(3919.73,-500.55) R131.1@3984.73,-500.55
NetR90_2: R90.2 R91.2 R92.1 | length 125
  Top Layer w15: R92.1@3121.23,284.45 R91.2@3121.23,349.45 R90.2@3121.23,409.45
NetR121_2: R121.2 R126.1 | length 145.8
  Bottom Layer w30: R126.1@4481.82,4904.45 R121.2@4627.65,4904.45
NetR122_1: R122.1 R125.2 | length 139.4
  Bottom Layer w20: R122.1@4659.73,-75.55 R122.1@4660.73,-76.55
  Bottom Layer w30: R125.2@4521.73,-75.55 R122.1@4659.73,-75.55
NetR123_1: R123.1 R124.2 | length 197.4
  Bottom Layer w30: R124.2@4541.82,4719.45 4541.82,4702.36 4571.82,4672.36 R123.1@4571.82,4534.45
NetR123_2: R123.2 R129.1 | length 155.8
  Bottom Layer w30: R129.1@4301.82,4534.45 R123.2@4457.65,4534.45
NetR124_1: R124.1 R126.2 | length 209.9
  Bottom Layer w30: R126.2@4367.65,4904.45 4367.65,4789.69 4427.65,4729.69 R124.1@4427.65,4719.45
NetR127_1: R127.1 R128.2 | length 129
  Bottom Layer w30: R128.2@4440.73,-418.54 R127.1@4440.73,-289.54
NetR128_1: R128.1 R130.2 | length 149.4
  Bottom Layer w20: R128.1@4440.73,-498.54 R128.1@4441.73,-497.54
  Bottom Layer w30: R130.2@4289.73,-500.55 R128.1@4437.73,-500.55
NetR130_1: R130.1 R131.2 | length 145
  Bottom Layer w30: R131.2@4064.73,-500.55 R130.1@4209.73,-500.55
NetR145_2: R145.2 R147.1 | length 67.7
  Bottom Layer w15: R147.1@1160.23,1331.99 1227.23,1331.99 R145.2@1227.73,1332.5
NetR149_1: R149.1 R151.2 U25.7 | length 382.1
  Top Layer w15: v2(1024,1228) 1095.73,1299.73 R151.2@1095.73,1335.23
  Bottom Layer w15: R149.1@950.73,1225.95 R149.1@952.76,1227.97 ; R149.1@952.76,1222.95 R149.1@952.76,1227.97 ; R149.1@952.79,1228 v2(1024,1228) ; U25.7@1018.04,1340.45 972.76,1340.45 952.76,1320.45 R149.1@952.76,1227.97
NetR152_1: R152.1 U25.1 | length 131.2
  Bottom Layer w15: U25.1@803.47,1290.45 860.55,1290.45 885,1266 R152.1@885,1226.5
NetR156_1: R156.1 R157.2 | length 64.7
  Bottom Layer w15: R157.2@587.76,1243.95 588.25,1244.45 R156.1@652.26,1244.45
NetR158_1: R158.1 U2.1 | length 178.8
  Top Layer w20: v2(490.51,3241.49) U2.1@490.51,3290.06
  Bottom Layer w20: R158.1@490,3371.5 490.51,3370.99 v2(490.51,3241.49)
NetR159_1: R159.1 U2.7 | length 84.4
  Top Layer w20: R159.1@532,3585.5 540.51,3576.99 U2.7@540.51,3504.62
NetR160_1: R160.1 U6.1 | length 117.1
  Top Layer w15: v2(1022.95,3294) 1022.47,3294.47 U6.1@1074.21,3294.47
  Bottom Layer w15: v2(1022.95,3294) 1079.42,3294 R160.1@1085.24,3299.82
NetR161_1: R161.1 U6.7 | length 131.5
  Top Layer w15: v2(1124,3573) 1124.21,3572.79 U6.7@1124.21,3509.04
  Bottom Layer w15: R161.1@1120.5,3507 1124,3510.5 v2(1124,3573)
NetR162_1: R162.1 U7.1 | length 181.8
  Top Layer w15: R162.1@1221.5,1833 1289.4,1900.91 U7.1@1375.17,1900.91
NetR163_1: R163.1 U7.7 | length 101.4
  Top Layer w15: v2(1096,1951) 1096.09,1950.91 U7.7@1160.6,1950.91
  Bottom Layer w15: 1075.5,1979.3 1075.5,1971.5 v2(1096,1951)
NetR164_2: R164.2 U19.5 | length 378.8
  Top Layer w15: v1@2428.73,3772.45 U19.5@2486.98,3772.45
  Bottom Layer w15: v1(2432,3772.45) 2432,3739.18 2464.73,3706.45 R164.2@2464.73,3465.5
NetR165_2: R165.2 U18.5 | length 527
  Top Layer w15: v1(2427.86,861.86) U18.5@2486.11,861.86
  Bottom Layer w15: v1(2427.86,861.86) 2462,896 R165.2@2462,1316.5
NetR166_2: R166.2 U17.5 | length 386.4
  Top Layer w15: v1(2427.73,2344.45) U17.5@2485.98,2344.45
  Bottom Layer w15: v1(2427.73,2344.45) 2427.73,2314.45 2462,2280.18 R166.2@2462,2030.5
NTC: R93.1 R106.2 U24.17 | length 2714
  Top Layer w15: R93.1@3121.23,224.45 3188.24,224.45 R106.2@3189.73,225.95 3251.23,287.45 3251.23,463.52 3292.16,504.45 3427.73,504.45 3882,958.72 4376.24,958.72 4636.98,1219.45 5236.54,1219.45 U24.17@5295.54,1160.45
OVERLOAD: J3.15 R11.1 R158.2 R159.2 R160.2 R161.2 R162.2 R163.2 U8.6 | length 4934.2
  Top Layer w15: R11.1@468.27,3647.05 469.72,3648.5 R159.2@532,3648.5 ; R162.2@1158.5,1833 1158.5,1786.5 v2(1159,1786) ; U8.6@1235.87,2227.6 1272.4,2227.6 1330.55,2169.45 v1(1424.73,2169.45) 1807.73,2169.45 J3.15@1847.73,2129.45
  Top Layer w20: v1(411.76,3647.05) R11.1@468.27,3647.05
  Bottom Layer w15: R158.2@490,3434.5 490,3554 411.76,3632.24 v1(411.76,3647.05) 1122.95,3647.05 1183.5,3586.5 ; R160.2@1148.23,3299.82 1183.5,3335.09 R161.2@1183.5,3507 1183.5,3586.5 ; v2(1159,1786) 1159,1826 1012.5,1972.5 R163.2@1012.5,2001 1012.5,2133.5 1048.45,2169.45 v1(1424.73,2169.45) 1424.73,2629.45 1594.73,2799.45 1594.73,3566.27 1516,3645 1242,3645 1183.5,3586.5
PWM_U_BOT: C106.1 R143.1 U19.2 | length 302.3
  Top Layer w15: v1@2418.61,3932.57 2428.73,3922.45 U19.2@2486.98,3922.45
  Bottom Layer w15: R143.1@2262.23,3848.99 2261.23,3849.99 C106.1@2261.23,3910.99 2277.69,3927.45 v1(2421.73,3927.45)
PWM_U_TOP: C105.1 R144.1 U19.1 | length 296.3
  Top Layer w15: v1(2421.73,3972.45) U19.1@2486.98,3972.45
  Bottom Layer w15: R144.1@2261.23,4036.45 C105.1@2261.23,3973.99 2271.77,3963.45 2412.73,3963.45 v1(2421.73,3972.45)
PWM_V_BOT: C102.1 R140.1 U17.2 | length 273.9
  Top Layer w15: v1@2427.73,2494.45 U17.2@2485.98,2494.45
  Bottom Layer w15: R140.1@2280.23,2424.45 C102.1@2280.23,2487.65 2292.03,2499.45 v1(2420.73,2499.45) v1@2415.73,2494.45
PWM_V_TOP: C101.1 R139.1 U17.1 | length 276.4
  Top Layer w15: v1(2420.73,2549.45) 2425.73,2544.45 U17.1@2485.98,2544.45
  Bottom Layer w15: R139.1@2281.23,2612.45 C101.1@2281.23,2550.99 2291.77,2540.45 2411.73,2540.45 v1(2420.73,2549.45)
PWM_W_BOT: C104.1 R142.1 U18.2 | length 288.9
  Top Layer w15: v1@2417.74,1021.99 2427.86,1011.86 U18.2@2486.11,1011.86
  Bottom Layer w12: C104.1@2279.23,1002.99 2293.1,1016.86 v1(2420.86,1016.86)
  Bottom Layer w15: R142.1@2278.23,934.45 2278.23,1001.99 C104.1@2279.23,1002.99
PWM_W_TOP: C103.1 R141.1 U18.1 | length 280.9
  Top Layer w15: v1(2420.86,1061.86) U18.1@2486.11,1061.86
  Bottom Layer w10: C103.1@2278.23,1068.99 C103.1@2279.23,1067.99
  Bottom Layer w15: R141.1@2276.73,1138.45 2276.73,1070.49 C103.1@2278.23,1068.99 ; C103.1@2279.23,1067.99 2285.36,1061.86 v1(2420.86,1061.86)
TRIP: J3.12 R63.2 U8.3 | length 640.9
  Top Layer w15: U8.3@1344.13,2302.4 1747.18,2302.4 R63.2@1757.73,2312.95 1789.24,2281.45 1899.73,2281.45 J3.12@1947.73,2329.45
U_BOT: R98.2 R99.2 R113.2 U24.3 | length 937.6
  Top Layer w20: R99.2@3200.08,3579.45 R98.2@3200.08,3684.45 ; R113.2@3548.73,3067.95 R113.2@3553.73,3062.95
  Top Layer w30: R99.2@3200.08,3579.45 3200.08,3521.92 3315,3407 3315,3203.18 3450.24,3067.95 R113.2@3548.73,3067.95 ; R113.2@3553.73,3062.95 3598.43,3062.95 U24.3@3645.93,3110.45
U_BOT_REF: C72.1 C73.1 R113.1 R132.1 U19.9 U24.4 | length 504.2
  Top Layer w20: C73.1@2859.24,3478.95 C72.1@2859.24,3552.45 2861,3554.21 U19.9@2861,3622.45 2917.55,3622.45 3050,3490 v1(3050,3487.5)
  Top Layer w30: R113.1@3548.73,2999.95 3606.43,2999.95 U24.4@3645.93,2960.45
U_PHASE: J14.3 R86.1 R118.1 | length 4068.2
  Top Layer w15: R86.1@3106.23,4696.58 3119.23,4709.58 3567.18,4709.58 3897.31,4379.45 5329.73,4379.45 v1(5434.73,4274.45) ; v1(5439.73,4379.45) 5444.73,4379.45 5464.73,4359.45 5814.73,4359.45 5864.73,4309.45 5864.73,4004.45 5791.73,3931.45 5699.73,3931.45 5673.73,3905.45 R118.1@5673.73,3449.45
  Bottom Layer w15: v1(5434.73,4274.45) 5439.73,4279.45 v1(5439.73,4379.45)
U_TOP: R104.2 R105.2 R112.2 U24.1 | length 916.5
  Top Layer w30: R105.2@3209.08,4028.45 3209.08,3925.71 R104.2@3208.82,3925.45 3417.73,3925.45 3491.73,3851.45 3491.73,3534.45 3513.24,3512.95 R112.2@3548.73,3512.95 3598.43,3512.95 U24.1@3645.93,3560.45
U_TOP_REF: C79.1 C80.1 C87.1 C98.1 J5.2 R78.2 R85.1 R112.1 R118.2 TP10.1 U13.4 U19.14 U20.3 U24.2 U24.23 U24.24 | length 5739.3
  Top Layer w15: U13.4@2889.3,4801.58 3091.86,4801.58 v1(3100.73,4810.45) v1@3106.23,4804.95 ; C87.1@3041.23,4624.45 v1(3100.73,4624.45) ; R85.1@3106.23,4761.58 3128.23,4739.58 3579.61,4739.58 3909.73,4409.45 5342.16,4409.45 5422.16,4329.45 5799.73,4329.45 5834.73,4294.45 5834.73,4024.45 5773.73,3963.45 5699.73,3963.45 5673.73,3989.45 R118.2@5673.73,4247.45
  Top Layer w20: U19.14@2861,3872.45 2909.73,3872.45 2921.73,3884.45 v1(2939.73,3884.45)
  Top Layer w30: v1(2939.73,3884.45) 2963.73,3860.45 3415.73,3860.45 3446.73,3829.45 3446.73,3505.45 3502.23,3449.95 R112.1@3548.73,3449.95 3606.43,3449.95 U24.2@3645.93,3410.45 ; C79.1@2942.23,4069.45 3014.45,4069.45 v1(3020,4075)
  Bottom Layer w20: v1(2939.73,3884.45) 2949.73,3884.45 2988.73,3923.45 2988.73,4023.45 2942.73,4069.45 2942.23,4069.45
  Bottom Layer w30: TP10.1@5989.73,4249.45 TP10.1@5994.73,4244.45
  Bottom Layer w90: R118.2@5673.73,4249.45 TP10.1@5989.73,4249.45
  other v1: 3020,4120 3020.73,4159.45
V_BOT: R94.2 R95.2 R115.2 U24.7 | length 576.3
  Top Layer w30: R94.2@3199.08,2256.45 R95.2@3199.08,2151.45 3210.57,2162.95 R115.2@3548.73,2162.95 3598.43,2162.95 U24.7@3645.93,2210.45
V_BOT_REF: C71.1 C74.1 R115.1 R133.1 U17.9 U24.8 | length 513.8
  Top Layer w20: C74.1@2858.24,2124.45 2860,2126.21 U17.9@2860,2194.45 2920.55,2194.45 v1(3055,2060) ; C74.1@2860.24,2126.45 2860.24,2053.95 C71.1@2864.73,2049.45
  Top Layer w30: R115.1@3548.73,2099.95 3606.43,2099.95 U24.8@3645.93,2060.45
V_DC: C9.1 J2.18 R8.2 R12.2 | length 981.9
  Top Layer w15: J2.18@241.73,2029.45 R12.2@405.73,2029.45 ; R8.2@335.73,2629.95 335.73,2658.45 336,2658.72 v1(336,2674)
  Bottom Layer w15: J2.18@241.73,2029.45 189.73,2081.45 189.73,2550 217.16,2577.43 297.43,2577.43 336,2616 v1(336,2674)
V_PHASE: J14.2 R88.1 R119.2 | length 3442.1
  Top Layer w15: R88.1@3108.58,3171.32 3121.58,3184.32 3188.43,3184.32 3209.86,3162.9 3209.86,3029.32 3479.73,2759.45 4264.73,2759.45 4684.73,2339.45 5369.73,2339.45 5549.73,2519.45 5647.73,2519.45 5673.73,2493.45 R119.2@5673.73,2135.45
V_TOP: R100.2 R102.2 R114.2 U24.5 | length 615.8
  Top Layer w30: R102.2@3208.08,2600.45 3208.08,2497.71 R100.2@3207.82,2497.45 3332.73,2497.45 3448.23,2612.95 R114.2@3548.73,2612.95 3622.43,2612.95 U24.5@3656.93,2647.45 ; U24.5@3644.93,2659.45 U24.5@3645.93,2660.45
V_TOP_REF: C77.1 C86.1 C90.1 C100.1 J6.2 R84.2 R87.1 R114.1 R119.1 TP8.1 U16.4 U17.14 U21.3 U24.6 U24.21 U24.22 | length 5065.1
  Top Layer w15: U16.4@2891.65,3276.32 3094.21,3276.32 v1(3103.08,3285.2) v1@3108.58,3279.7 ; C90.1@3051.23,3104.45 v1(3112.73,3104.45) ; R87.1@3108.58,3236.32 3130.58,3214.32 3200.86,3214.32 3239.86,3175.32 3239.86,3044.32 3494.73,2789.45 4277.16,2789.45 4697.16,2369.45 5357.31,2369.45 5539.31,2551.45 5647.73,2551.45 5673.73,2577.45 R119.1@5673.73,2935.45 ; U24.21@5289.73,2510.45 U24.21@5295.54,2510.45
  Top Layer w20: U17.14@2860,2444.45 2908.73,2444.45 2920.73,2456.45 v1(2938.73,2456.45)
  Top Layer w30: C77.1@2938.23,2634.45 3004.45,2634.45 3020,2650 v1(3020,2660) ; v1(2938.73,2456.45) 2962.73,2432.45 3355.73,2432.45 3473.24,2549.95 R114.1@3548.73,2549.95 3606.43,2549.95 U24.6@3645.93,2510.45
  Bottom Layer w20: 2938.23,2634.45 2984.73,2587.95 2984.73,2502.45 v1(2938.73,2456.45)
  Bottom Layer w30: TP8.1@5673.73,3083.45 TP8.1@5674.73,3084.45
  Bottom Layer w90: R119.1@5673.73,2935.45 TP8.1@5673.73,3083.45
  other v1: 3019.73,2731.45
VCC_U: C79.2 C98.2 J5.1 R72.1 R136.1 U19.16 | length 512
  Top Layer w20: v1(2858.73,4019.45) 2858.73,3974.71 U19.16@2861,3972.45 2929.73,3972.45 v1(2930.73,3973.45)
  Top Layer w30: v1(2858.73,4019.45) 2879.24,4039.95 C79.2@2879.24,4069.45
  Bottom Layer w30: v1(2871.73,4357.45) 2889.73,4339.45 J5.1@3199.73,4339.45
  other v1: 2870.73,4306.45 2871.73,4412.45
